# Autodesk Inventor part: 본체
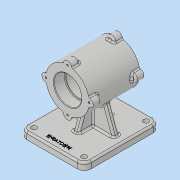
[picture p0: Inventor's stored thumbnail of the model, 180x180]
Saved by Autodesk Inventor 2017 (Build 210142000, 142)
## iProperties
Part Number: 본체
Material: 일반
Document SubType Name: Modeling
Designer: MRC
Density: 1 g/cm^3
Appearance: 기본값
Author: MRC
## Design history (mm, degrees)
sketch "스케치1"
  geometry: L1 (0, 43.5)-(0, -43.5); L2 (23.5, 43.5)-(37, 43.5); L3 (37, 43.5)-(37, -43.5); L4 (37, -43.5)-(23.5, -43.5); L5 (23.5, 43.5)-(23.5, 24.5); L6 (23.5, 24.5)-(21, 24.5); L7 (21, 24.5)-(21, -24.5); L8 (21, -24.5)-(23.5, -24.5); L9 (23.5, -24.5)-(23.5, -43.5); 2 further points
  constraints: 18 end point, 5 perpendicular, 4 point on line, 2 vertical, 1 coincident, 1 collinear, 1 horizontal, 1 midpoint
  dimensions: "d0" = 87 distance of L1.start L1.end; "d2" = 74 diameter of L3 L1; "d3" = 47 diameter of L5 L1; "d4" = 42 diameter of L7 L1; "d5" = 19 distance of L2.start L5.end
revolve "회전1" sketch "스케치1" stored, may be unused: angle "d6" = 90 deg
sketch "스케치2"
  geometry: C1 r 7 at (0, 37); 2 further points
  constraints: 2 vertical alignment, 1 centre point, 1 other
  dimensions: "d7" = 14 diameter of C1
extrude "돌출1" join sketch "스케치2" distance "d8" = 14; taper "d9" = 0 deg
hole "구멍1" diameter "d12" = 3.242; stored, may be unused: countersink angle "d16" = 90 deg, drill point angle "d18" = 118 deg; dims "d10" = 10, "d11" = 10, "d13" = 8, "d14" = 4, "d15" = 2, "d17" = 10
node "작업 평면1"
sketch "스케치3"
  geometry: L1 (55, 70)-(-55, 70); L2 (-55, 70)-(-55, -60); L3 (-55, -60)-(55, -60); L4 (55, -60)-(55, 70); 2 further points
  constraints: 8 end point, 2 parallel, 1 horizontal, 1 midpoint, 1 perpendicular, 1 vertical alignment
  dimensions: "d23" = 130 distance of L3.end L1.start; "d24" = 110 distance of L2.end L3.end; "d25" = 70 distance from line of L1 point (0, 0)
extrude "돌출2" join sketch "스케치3" distance "d26" = 12; taper "d27" = 0 deg
fillet "모깎기1" dims "d28" = 12
sketch "스케치4"
  geometry: L1 (-55, 48)-(-55, -58) reference; L2 (-43, -70)-(43, -70) reference; L3 (55, -58)-(55, 48) reference; L4 (43, 60)-(-43, 60) reference; C1 r 4.5 at (-43, -58); C2 r 4.5 at (-43, 48); C3 r 4.5 at (43, 48); C4 r 4.5 at (43, -58); A1 r 12 centre (-43, 48) between (-43, 60) and (-55, 48) reference; A2 r 12 centre (-43, -58) between (-55, -58) and (-43, -70) reference; A3 r 12 centre (43, -58) between (43, -70) and (55, -58) reference; A4 r 12 centre (43, 48) between (55, 48) and (43, 60) reference; 1 further point
  constraints: 4 centre point, 4 coincident
  dimensions: "d29" = 9 diameter of C1; "d30" = 9 diameter of C2; "d31" = 9 diameter of C3; "d32" = 9 diameter of C4
extrude "돌출3" cut sketch "스케치4" stored distance "d33" = 12; taper "d34" = 0 deg
sketch "스케치5"
  geometry: 2 further points
  constraints: 1 vertical alignment, 1 other
  dimensions: "d35" = 58 distance of point (0, -58) point (0, 0)
feature "엠보싱1" sketch "스케치5" dims "d0" = 87, "d2" = 74, "d3" = 47, "d4" = 42, "d5" = 19, "d18" = 118 deg, "d36" = 0.5, "d37" = 0
sketch "스케치7"
  geometry: C1 r 5 at (0, 0); 1 further point
  constraints: 1 centre point, 1 coincident
  dimensions: "d41" = 10 diameter of C1
extrude "돌출4" join sketch "스케치7" stored distance "d42" = 12; taper "d43" = 0 deg
sketch "스케치6"
  geometry: L1 (-41, -70)-(-26.715, -30.753); L2 (-55, -70)-(-43, -70) reference; L3 (-55, -70)-(-55, -82) reference; L4 (-43, -70)-(43, -70) reference; 1 further point
  constraints: 2 end point, 1 point on line
  dimensions: "d39" = 14 distance from line of L1.start L3; "d40" = 110 deg angle of L2 L1
feature "리브1" sketch "스케치6" dims "d44" = 1, "d45" = 10, "d46" = 0, "d47" = 0, "d48" = 1, "d49" = 1
sketch "스케치8"
  geometry: L1 (-70, 30)-(-43.861, 20.486); L2 (-70, 58)-(-70, -48) reference; 1 further point
  constraints: 2 end point, 1 point on line
  dimensions: "d50" = 110 deg angle of L1 L2; "d51" = 30 vertical distance of L1.start point (0, 0)
feature "리브2" sketch "스케치8" dims "d52" = 1, "d53" = 10, "d54" = 0, "d55" = 0, "d56" = 1, "d57" = 1
chamfer "모따기1" distance "d58" = 1; stored, may be unused: second distance "d59" = 2, angle "d60" = 45 deg
fillet "모깎기2" dims "d61" = 3
fillet "모깎기3" dims "d62" = 3
fillet "모깎기4" dims "d63" = 3
fillet "모깎기5" dims "d64" = 1
node "솔리드1"
pattern_circular "원형 패턴1" dims angle "d20" = 360 deg
mirror "미러1"
mirror "미러2"
mirror "미러3"
node "투영된 루프1"
other parameters: "d22" = -82
